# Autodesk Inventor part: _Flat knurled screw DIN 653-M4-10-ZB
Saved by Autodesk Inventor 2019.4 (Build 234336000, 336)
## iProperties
Created: 2021-08
Part Number: _Flat knurled screw DIN 653-M4-10-ZB
Material: Generic
Document SubType Name: Modeling
Designer: Administrator
Density: 1 g/cm^3
Appearance: Default
Title: _Flat knurled screw DIN 653-M4-10-ZB
Author: Administrator
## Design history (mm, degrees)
feature "Body1"
body "Solid1"
